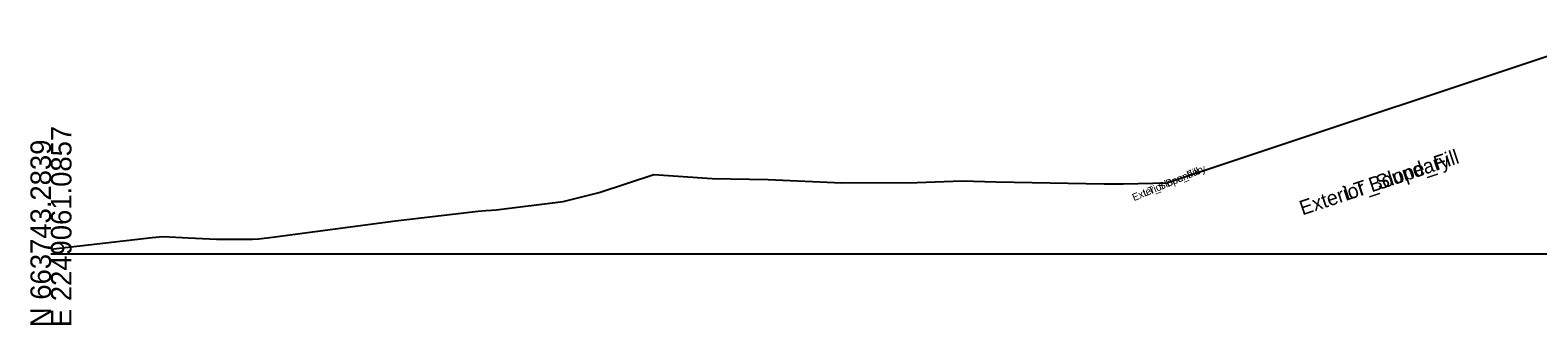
# Model space of a CAD drawing. Extents: x -26 to 2603, y -10 to 9566.
# Drawn here: x 997.2 to 1203, y 6490.3 to 6530.6 of the extents above; entities that cross this region are included whole.
import ezdxf

# ---------------------------------------------------------------- set-up
doc = ezdxf.new("R2010")
doc.units = 0
for name, color, linetype in [('Default', 7, 'Continuous'), ('Exist Cross Section Cell', 7, 'Continuous'), ('Exist XS Ground Line', 7, 'Continuous'), ('Scratch_Level_9', 7, 'Continuous')]:
    doc.layers.add(name, color=color, linetype=linetype)

msp = doc.modelspace()

# ---------------------------------------------------------------- linework, layer by layer
at = {"layer": 'Exist Cross Section Cell'}
msp.add_line((1000, 6500), (1300, 6500), dxfattribs=at)
at = {"layer": 'Exist XS Ground Line'}
for p, q in [((1074.83, 6508.36), (1082.33, 6510.82)), ((1082.33, 6510.82), (1090.27, 6510.3)), ((1090.27, 6510.3), (1097.91, 6510.15)), ((1097.91, 6510.15), (1107.97, 6509.71)), ((1107.97, 6509.71), (1118.27, 6509.74)), ((1118.27, 6509.74), (1124.42, 6509.97)), ((1124.42, 6509.97), (1129.05, 6509.82)), ((1129.05, 6509.82), (1143.81, 6509.57)), ((1143.81, 6509.57), (1146.39, 6509.57)), ((1146.39, 6509.57), (1152.48, 6509.7)), ((1060.8, 6506.01), (1069.91, 6507.15)), ((1069.91, 6507.15), (1074.83, 6508.36)), ((1047.04, 6504.53), (1058.33, 6505.83)), ((1058.33, 6505.83), (1059.36, 6505.94)), ((1059.36, 6505.94), (1060.16, 6505.97)), ((1060.16, 6505.97), (1060.8, 6506.01)), ((1030.25, 6502.3), (1047.04, 6504.53)), ((1000, 6500.65), (1013.8, 6502.22)), ((1013.8, 6502.22), (1015.28, 6502.38)), ((1015.28, 6502.38), (1018.8, 6502.21)), ((1018.8, 6502.21), (1022.59, 6502.03)), ((1022.59, 6502.03), (1023.01, 6502.02)), ((1023.01, 6502.02), (1027.51, 6502.02)), ((1027.51, 6502.02), (1028.39, 6502.04)), ((1028.39, 6502.04), (1030.25, 6502.3))]:
    msp.add_line(p, q, dxfattribs=at)
msp.add_lwpolyline([(1215.05, 6530.55), (1152.48, 6509.7)], dxfattribs=at)

# ---------------------------------------------------------------- texts
at = {"layer": 'Default'}
msp.add_text('-', height=0.0001, dxfattribs=at).set_placement((1000, 6500))
msp.add_text('-', height=0.0001, dxfattribs=at).set_placement((1000, 6500))
msp.add_text('-', height=0.0001, dxfattribs=at).set_placement((1000, 6500))
msp.add_text('-', height=0.0001, dxfattribs=at).set_placement((1000, 6500))
msp.add_text('-', height=0.0001, dxfattribs=at).set_placement((1000, 6500))
at = {"layer": 'Exist Cross Section Cell'}
for s, p in [('E 2249061.0857', (1002.8, 6490)), ('N 663743.2839', (1000, 6490))]:
    msp.add_text(s, height=2.8, rotation=90, dxfattribs=at).set_placement(p)
at = {"layer": 'Scratch_Level_9'}
for s, height, rotation, p in [('Exterior Boundary', 2, 18.4332, (1170.86, 6505.24)), ('Exterior Boundary', 2, 18.4332, (1170.86, 6505.24)), ('LT_Slope_Fill', 2, 18.4332, (1176.91, 6507.26)), ('LT_Slope_Fill', 2, 18.4332, (1176.91, 6507.26)), ('Exterior Boundary', 1, 22.5575, (1147.88, 6507.19)), ('Exterior Boundary', 1, 22.5575, (1147.88, 6507.19)), ('LT_Slope_Fill', 1, 22.5575, (1149.34, 6507.8)), ('LT_Slope_Fill', 1, 22.5575, (1149.34, 6507.8))]:
    msp.add_text(s, height=height, rotation=rotation, dxfattribs=at).set_placement(p)

doc.saveas('drawing.dxf')
